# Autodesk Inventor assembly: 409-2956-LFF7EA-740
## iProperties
Created: 2010-09
Part Number: 409-2956-LFF7EA-740
Document SubType Name: Weldment
Designer: S. Boerckel
Weld Material: Welded Steel Mild
Mass: 33077.7 g
Surface Area: 13370.5 cm^2
Volume: 4199.89 cm^3
Density: 7.87585 g/cm^3
Description: DISCHARGE SPOOL
User Status: WELD
Material: WELDMENT
SMR: =<MATERIAL>
Author: S. Boerckel
Revision Number: B
